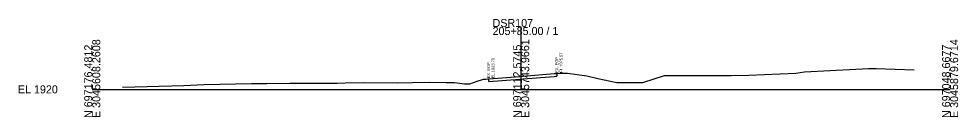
# Model space of a CAD drawing. Extents: x -26 to 19003, y -31 to 24541.
# Drawn here: x 1974.3 to 2302.8, y 5990.3 to 6024.6 of the extents above; entities that cross this region are included whole.
import ezdxf

# ---------------------------------------------------------------- set-up
doc = ezdxf.new("R2010")
doc.units = 0
for name, color, linetype in [('DESIGN - SHEET - Light Grid', 7, 'Continuous'), ('SURVEY - GROUND - Existing Pavement Layer', 7, 'Continuous'), ('SURVEY - GROUND - Existing Pavement Text', 7, 'Continuous'), ('SURVEY - GROUND - Top of Ground', 7, 'Continuous')]:
    doc.layers.add(name, color=color, linetype=linetype)

msp = doc.modelspace()

# ---------------------------------------------------------------- linework, layer by layer
at = {"layer": 'DESIGN - SHEET - Light Grid'}
for p, q in [((2150, 6000), (2150, 6021.76)), ((2000, 6000), (2150, 6000)), ((2150, 6000), (2300, 6000))]:
    msp.add_line(p, q, dxfattribs=at)
at = {"layer": 'SURVEY - GROUND - Existing Pavement Layer'}
for p, q in [((2138.64, 6002.7), (2138.64, 6003.7)), ((2138.64, 6002.7), (2149.55, 6003.54)), ((2149.55, 6003.54), (2150, 6003.58)), ((2150, 6003.58), (2150.75, 6003.64)), ((2150.75, 6003.64), (2161.55, 6004.51)), ((2161.55, 6004.51), (2162.1, 6004.55)), ((2162.1, 6004.55), (2162.44, 6004.57)), ((2162.44, 6005.57), (2162.44, 6004.57))]:
    msp.add_line(p, q, dxfattribs=at)
at = {"layer": 'SURVEY - GROUND - Top of Ground'}
msp.add_lwpolyline([(2010.62, 6000.81), (2031.98, 6001.35), (2039.04, 6001.7), (2055.74, 6002.01), (2060.17, 6002.05), (2061.02, 6002.06), (2069.07, 6002.12), (2069.59, 6002.13), (2072.83, 6002.15), (2073.15, 6002.17), (2073.58, 6002.18), (2084.29, 6002.2), (2085.67, 6002.19), (2088.42, 6002.24), (2095.31, 6002.34), (2106.64, 6002.33), (2112.01, 6002.38), (2118.1, 6002.53), (2123.73, 6002.42), (2126.7, 6002.42), (2128.58, 6002.2), (2130.16, 6001.95), (2131.22, 6001.97), (2132.07, 6001.98), (2134.64, 6002.83), (2136.44, 6003.47), (2136.88, 6003.52), (2137.61, 6003.58), (2138.27, 6003.65), (2138.64, 6003.7), (2149.55, 6004.54), (2150, 6004.58), (2150.75, 6004.64), (2161.55, 6005.51), (2162.1, 6005.55), (2162.44, 6005.57), (2163.66, 6005.64), (2166.25, 6005.6), (2172.94, 6004.75), (2176.77, 6003.81), (2183.49, 6002.35), (2190.06, 6002.42), (2192.57, 6002.45), (2200.07, 6004.81), (2206.36, 6004.81), (2223.42, 6004.87), (2229.56, 6005), (2246.03, 6005.64), (2249.11, 6006.06), (2267.06, 6007), (2271.41, 6007.25), (2274.19, 6007.24), (2287.49, 6006.83)], dxfattribs=at)

# ---------------------------------------------------------------- texts
at = {"layer": 'DESIGN - SHEET - Light Grid'}
for s, p in [('DSR107', (2140, 6021.76)), ('205+85.00 / 1', (2140, 6018.96)), ('EL 1920', (1974, 5998.6))]:
    msp.add_text(s, height=2.8, dxfattribs=at).set_placement(p)
for s, p in [('E 3045608.2608', (2002.8, 5990)), ('N 697112.5745', (2150, 5990)), ('E 3045743.9661', (2152.8, 5990)), ('E 3045879.6714', (2302.8, 5990)), ('N 697176.4812', (2000, 5990)), ('N 697048.6677', (2300, 5990))]:
    msp.add_text(s, height=2.8, rotation=90, dxfattribs=at).set_placement(p)
at = {"layer": 'SURVEY - GROUND - Existing Pavement Text'}
for s, p in [('EL.1925.57', (2164.45, 6005.77)), ('EX. EOP', (2139.14, 6003.9)), ('EL.1923.70', (2140.64, 6003.9)), ('EX. EOP', (2162.94, 6005.77))]:
    msp.add_text(s, height=1, rotation=90, dxfattribs=at).set_placement(p)

doc.saveas('drawing.dxf')
